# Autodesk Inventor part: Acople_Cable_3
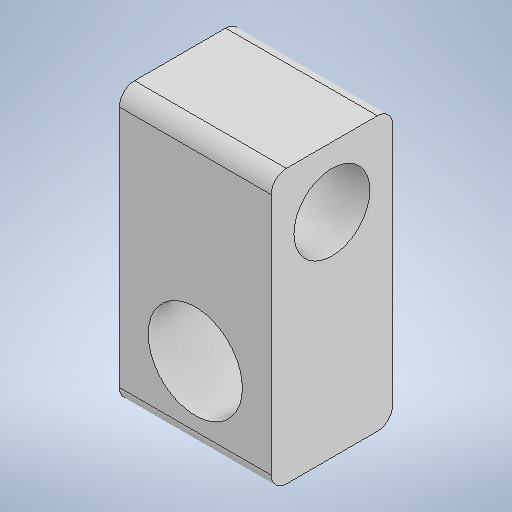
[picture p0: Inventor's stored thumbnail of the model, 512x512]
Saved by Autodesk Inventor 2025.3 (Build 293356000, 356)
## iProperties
Created: 2025-12
Part Number: Acople_Cable_3
Material: Genérico
Document SubType Name: Modeling
Designer: Dell
Density: 1 g/cm^3
Appearance: Valor por defecto
Author: Dell
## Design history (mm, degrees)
sketch "Boceto1"
  geometry: L1 (-5, 5)-(5, 5); L2 (5, 5)-(5, -5); L3 (5, -5)-(-5, -5); L4 (-5, -5)-(-5, 5); L5 (-5, 5)-(5, -5); L6 (5, 5)-(-5, -5); C1 r 3.1 at (0, 0); 1 further point
  constraints: 12 end point, 2 midpoint, 2 parallel, 1 centre point, 1 coincident, 1 horizontal, 1 perpendicular
  dimensions: "d0" = 6.2 diameter of C1; "d1" = 10 distance of L2.end L3.end; "d2" = 10 distance of L1.end L2.end
extrude "Extrusión1" new body sketch "Boceto1" distance "d3" = 8; taper "d4" = 0 deg
sketch "Boceto2"
  geometry: L1 (0, 0)-(10, 0) reference; L2 (0, -8)-(10, -8) reference; L3 (0, 0)-(10, 0); L4 (10, 0)-(10, -8); L5 (10, -8)-(0, -8); L6 (0, -8)-(0, 0); 3 further points
  constraints: 8 end point, 2 parallel, 1 horizontal, 1 perpendicular
extrude "Extrusión2" join sketch "Boceto2" distance "d5" = 8; taper "d6" = 0 deg
sketch "Boceto3"
  geometry: L1 (0, 0)-(8, 0) reference; L2 (0, 0)-(0, 18) reference; L3 (8, 0)-(8, 18) reference; C1 r 2.5 at (4, 14); 1 further point
  constraints: 1 centre point
  dimensions: "d8" = 5 diameter of C1
extrude "Extrusión3" cut sketch "Boceto3" distance "d9" = 10; taper "d10" = 0 deg
fillet "Empalme1" dims "d11" = 1
node "Sólido1"
